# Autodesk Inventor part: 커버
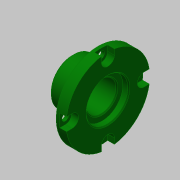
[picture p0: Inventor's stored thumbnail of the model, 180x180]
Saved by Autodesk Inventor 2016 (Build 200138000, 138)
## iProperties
Created: 2019-10
Part Number: 커버
Material: 알루미늄 6061
Document SubType Name: Modeling
Designer: mduedu
Density: 1 g/cm^3
Appearance: 진녹색
Author: mduedu
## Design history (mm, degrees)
sketch "스케치1"
  geometry: L1 (0, 0)-(-18, 0); L2 (-18, 0)-(-18, 11.5); L3 (-18, 11.5)-(-5, 11.5); L4 (-5, 11.5)-(-5, 21); L5 (-5, 21)-(0, 21); L6 (0, 21)-(0, 0)
  constraints: 12 end point, 3 parallel, 2 perpendicular, 1 horizontal
  dimensions: "d0" = 18 distance of L1.start L1.end; "d1" = 42 diameter of L5 L1; "d2" = 23 diameter of L3 L1; "d3" = 13 distance of L2.end L3.end
revolve "회전1" sketch "스케치1" stored, may be unused: angle "d4" = 90 deg
hole "구멍1" diameter "d7" = 15; stored, may be unused: countersink angle "d11" = 90 deg, drill point angle "d13" = 118 deg; dims "d5" = 10, "d6" = 10, "d8" = 6, "d9" = 21, "d10" = 3, "d12" = 8
chamfer "모따기1" distance "d14" = 1; stored, may be unused: second distance "d15" = 2, angle "d16" = 45 deg
sketch "스케치2" dims "d17" = 36
  geometry: 6 further points
  constraints: 2 vertical alignment, 1 coincident, 7 other
  dimensions: "d20" = 360 deg dimension on point (0, 0) point (0, 18) (derived)
sketch "스케치3"
  geometry: 4 further points
  constraints: 4 other
hole "구멍2" sketch "스케치3" at (-18, 0), (0, -18), (18, 0), (0, 18) diameter "d22" = 3.4; stored, may be unused: countersink angle "d26" = 90 deg, drill point angle "d28" = 0 deg; dims "d23" = 6, "d24" = 6.5, "d25" = 3.4, "d27" = 8
sketch "스케치4"
  geometry: L1 (-21.25, 20.747)-(-21.25, 18); L2 (-14.75, 18)-(-14.75, 20.747); A1 r 3.25 centre (-18, 18) between (-19.349, 20.957) and (-16.651, 20.957) reference; A2 r 21 centre (-18, 0) between (-19.349, 20.957) and (-38.957, 1.349) reference; A3 r 21 centre (-18, 0) between (2.957, 1.349) and (-16.651, 20.957) reference; A4 r 21 centre (-18, 0) between (-14.75, 20.747) and (-21.25, 20.747); A5 r 3.25 centre (-18, 18) between (-21.25, 18) and (-14.75, 18); 1 further point
  constraints: 8 point on circle, 4 end point, 2 centre point, 2 coincident, 2 tangent, 1 parallel, 1 vertical
extrude "돌출1" cut sketch "스케치4" stored distance "d29" = 10; taper "d30" = 0 deg
chamfer "모따기3" distance "d37" = 0.5; stored, may be unused: second distance "d38" = 2, angle "d39" = 45 deg
chamfer "모따기4" distance "d40" = 0.5; stored, may be unused: second distance "d41" = 2, angle "d42" = 45 deg
node "솔리드1"
pattern_circular "원형 패턴1" dims angle "d32" = 360 deg
